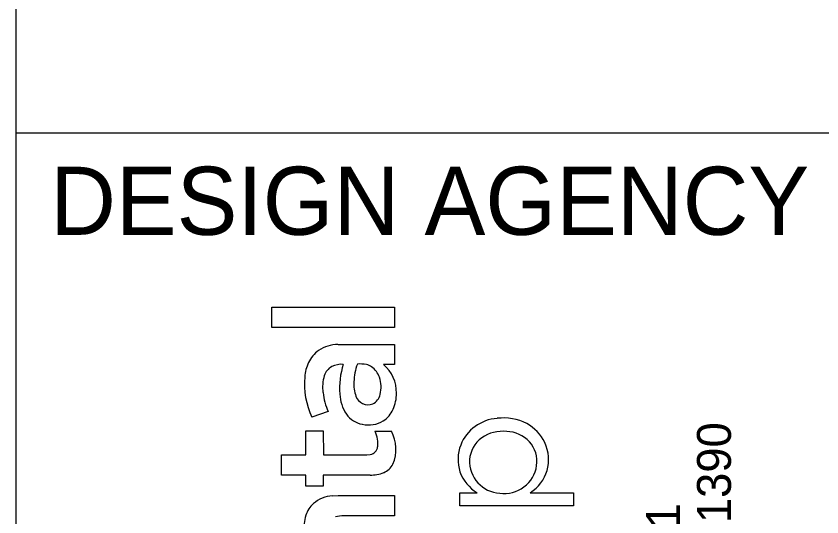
# Model space of a CAD drawing. Extents: x -0.6 to 34, y 0 to 22.
# Drawn here: x 32 to 33.183, y 3.936 to 4.671 of the extents above; entities that cross this region are included whole.
import ezdxf

# ---------------------------------------------------------------- set-up
doc = ezdxf.new("R2010")
doc.units = 0
doc.layers.add('SH_Cut_Line', color=7, linetype='Continuous')
doc.layers.add('SH_Data', color=7, linetype='Continuous')

msp = doc.modelspace()

# ---------------------------------------------------------------- linework, layer by layer
at = {"layer": 'SH_Cut_Line'}
for p, q in [((32.3756, 4.2141), (32.3756, 4.244)), ((32.3756, 4.244), (32.5557, 4.244)), ((32.5557, 4.244), (32.5557, 4.2141)), ((32.5557, 4.2141), (32.3756, 4.2141)), ((32.4727, 4.189), (32.5555, 4.1892)), ((32.5555, 4.1892), (32.5557, 4.1596)), ((32.5557, 4.1596), (32.5397, 4.1596)), ((32.4582, 4.0904), (32.4343, 4.0823)), ((32.4254, 4.027), (32.4255, 4.0621)), ((32.4255, 4.0621), (32.4511, 4.0621)), ((32.4511, 4.0621), (32.4512, 4.027)), ((32.527, 4.0616), (32.5511, 4.0616)), ((32.3896, 3.9972), (32.3896, 4.027)), ((32.3896, 4.027), (32.4254, 4.027)), ((32.4512, 4.027), (32.515, 4.027)), ((32.515, 4.027), (32.52, 4.0275)), ((32.4254, 3.9972), (32.3896, 3.9972)), ((32.4254, 3.9807), (32.4254, 3.9972)), ((32.5197, 3.9972), (32.4511, 3.9972)), ((32.4511, 3.9972), (32.4511, 3.9807)), ((32.4511, 3.9807), (32.4254, 3.9807)), ((32.4644, 3.9669), (32.4729, 3.9673)), ((32.4729, 3.9673), (32.5557, 3.9673)), ((32.5557, 3.9673), (32.5557, 3.9375)), ((32.6515, 3.9521), (32.6515, 3.9711)), ((32.6515, 3.9711), (32.6771, 3.9711)), ((32.7549, 3.9713), (32.8186, 3.9711)), ((32.8186, 3.9711), (32.8184, 3.9521)), ((32.8184, 3.9521), (32.6515, 3.9521)), ((32.5557, 3.9375), (32.4814, 3.9375))]:
    msp.add_line(p, q, dxfattribs=at)
msp.add_lwpolyline([(32.3756, 4.2141), (32.3756, 4.244), (32.5557, 4.244), (32.5557, 4.2141)], close=True, dxfattribs=at)
for points in [[(32.4727, 4.189), (32.5555, 4.1892), (32.5557, 4.1596)], [(32.5557, 4.1596), (32.5397, 4.1596)], [(32.4582, 4.0904), (32.4343, 4.0823)], [(32.5197, 3.9972), (32.4511, 3.9972), (32.4511, 3.9807), (32.4254, 3.9807), (32.4254, 3.9972), (32.3896, 3.9972), (32.3896, 4.027), (32.4254, 4.027), (32.4255, 4.0621), (32.4511, 4.0621), (32.4512, 4.027), (32.515, 4.027), (32.52, 4.0275)], [(32.527, 4.0616), (32.5511, 4.0616)], [(32.4644, 3.9669), (32.4729, 3.9673), (32.5557, 3.9673), (32.5557, 3.9375), (32.4814, 3.9375)], [(32.7549, 3.9713), (32.8186, 3.9711), (32.8184, 3.9521), (32.6515, 3.9521)], [(32.6515, 3.9521), (32.6515, 3.9711), (32.6771, 3.9711)]]:
    msp.add_lwpolyline(points, dxfattribs=at)
for centre, radius, start, end in [((32.4745, 4.1326), 0.0565, 91.8942, 122.6317), ((32.4745, 4.1326), 0.0565, 91.8942, 122.6317), ((32.4685, 4.1447), 0.043, 124.537, 155.6594), ((32.4685, 4.1447), 0.043, 124.537, 155.6594), ((32.4882, 4.1361), 0.0646, 155.9764, 175.3149), ((32.4882, 4.1361), 0.0646, 155.9764, 175.3149), ((32.4753, 4.1356), 0.024, 119.4252, 161.6629), ((32.4753, 4.1356), 0.024, 119.4252, 161.6629), ((32.4779, 4.1278), 0.0321, 85.3802, 116.6222), ((32.4779, 4.1278), 0.0321, 85.3802, 116.6222), ((32.5879, 4.1251), 0.1129, 162.0821, 184.5285), ((32.5879, 4.1251), 0.1129, 162.0821, 184.5285), ((32.5801, 4.1313), 0.0841, 159.8366, 178.0362), ((32.5801, 4.1313), 0.0841, 159.8366, 178.0362), ((32.5051, 4.1074), 0.053, 79.6696, 94.2322), ((32.5051, 4.1074), 0.053, 79.6696, 94.2322), ((32.5089, 4.1364), 0.0238, 56.8913, 76.2149), ((32.5089, 4.1364), 0.0238, 56.8913, 76.2149), ((32.5052, 4.1318), 0.0297, 17.5984, 55.7282), ((32.5052, 4.1318), 0.0297, 17.5984, 55.7282), ((32.5055, 4.1191), 0.0529, 358.0746, 49.762), ((32.5055, 4.1191), 0.0529, 358.0746, 49.762), ((32.5364, 4.1308), 0.113, 174.6101, 205.3899), ((32.5364, 4.1308), 0.113, 174.6101, 205.3899), ((32.5076, 4.1265), 0.0576, 163.1369, 188.1675), ((32.5076, 4.1265), 0.0576, 163.1369, 188.1675), ((32.5466, 4.1303), 0.0506, 175.5903, 199.8857), ((32.5466, 4.1303), 0.0506, 175.5903, 199.8857), ((32.4916, 4.1264), 0.0443, 345.9408, 18.9919), ((32.4916, 4.1264), 0.0443, 345.9408, 18.9919), ((32.5473, 4.1297), 0.0973, 186.7598, 203.7981), ((32.5473, 4.1297), 0.0973, 186.7598, 203.7981), ((32.5328, 4.1187), 0.0575, 182.5676, 213.7144), ((32.5328, 4.1187), 0.0575, 182.5676, 213.7144), ((32.5164, 4.1189), 0.0184, 198.2844, 293.3081), ((32.5164, 4.1189), 0.0184, 198.2844, 293.3081), ((32.5152, 4.1199), 0.0199, 295.2883, 347.4639), ((32.5152, 4.1199), 0.0199, 295.2883, 347.4639), ((32.5019, 4.1168), 0.0566, 336.016, 0.5951), ((32.5019, 4.1168), 0.0566, 336.016, 0.5951), ((32.5149, 4.1078), 0.0366, 215.0668, 259.8133), ((32.5149, 4.1078), 0.0366, 215.0668, 259.8133), ((32.5175, 4.1097), 0.0394, 303.4436, 336.18), ((32.5175, 4.1097), 0.0394, 303.4436, 336.18), ((32.5175, 4.1131), 0.0423, 257.5256, 300.882), ((32.5175, 4.1131), 0.0423, 257.5256, 300.882), ((32.7108, 4.0182), 0.0624, 93.9866, 158.3119), ((32.7108, 4.0182), 0.0624, 93.9866, 158.3119), ((32.7156, 4.0065), 0.0746, 62.6889, 97.0135), ((32.7156, 4.0065), 0.0746, 62.6889, 97.0135), ((32.7212, 4.0191), 0.0608, 25.0657, 61.9602), ((32.7212, 4.0191), 0.0608, 25.0657, 61.9602), ((32.4863, 4.042), 0.0452, 10.1545, 25.723), ((32.4863, 4.042), 0.0452, 10.1545, 25.723), ((32.503, 4.0351), 0.0549, 336.589, 28.8991), ((32.503, 4.0351), 0.0549, 336.589, 28.8991), ((32.7138, 4.0102), 0.0513, 87.8965, 131.1812), ((32.7138, 4.0102), 0.0513, 87.8965, 131.1812), ((32.7175, 4.0102), 0.0513, 49.9089, 92.0363), ((32.7175, 4.0102), 0.0513, 49.9089, 92.0363), ((32.4957, 4.0436), 0.0356, 351.914, 10.2059), ((32.4957, 4.0436), 0.0356, 351.914, 10.2059), ((32.7092, 4.0167), 0.0434, 132.3289, 182.0949), ((32.7092, 4.0167), 0.0434, 132.3289, 182.0949), ((32.7215, 4.0173), 0.0433, 358.0487, 47.9447), ((32.7215, 4.0173), 0.0433, 358.0487, 47.9447), ((32.5184, 4.04), 0.0126, 277.6142, 353.7918), ((32.5184, 4.04), 0.0126, 277.6142, 353.7918), ((32.707, 4.0202), 0.0581, 158.656, 198.171), ((32.707, 4.0202), 0.0581, 158.656, 198.171), ((32.7245, 4.02), 0.0574, 301.9776, 25.6418), ((32.7245, 4.02), 0.0574, 301.9776, 25.6418), ((32.5291, 4.0261), 0.0275, 292.6889, 332.0598), ((32.5291, 4.0261), 0.0275, 292.6889, 332.0598), ((32.7135, 4.0181), 0.0478, 183.5974, 271.7045), ((32.7135, 4.0181), 0.0478, 183.5974, 271.7045), ((32.7172, 4.018), 0.0477, 267.3149, 357.4019), ((32.7172, 4.018), 0.0477, 267.3149, 357.4019), ((32.5209, 4.0486), 0.0514, 268.6727, 291.5235), ((32.5209, 4.0486), 0.0514, 268.6727, 291.5235), ((32.7103, 4.0243), 0.0627, 200.8399, 238.0162), ((32.7103, 4.0243), 0.0627, 200.8399, 238.0162), ((32.4687, 3.9172), 0.0499, 94.9706, 130.2248), ((32.4687, 3.9172), 0.0499, 94.9706, 130.2248), ((32.4635, 3.9255), 0.0402, 132.2238, 161.6823), ((32.4635, 3.9255), 0.0402, 132.2238, 161.6823), ((32.4787, 3.9211), 0.056, 162.274, 187.7917), ((32.4787, 3.9211), 0.056, 162.274, 187.7917), ((32.4811, 3.8915), 0.046, 89.6051, 105.3303), ((32.4811, 3.8915), 0.046, 89.6051, 105.3303)]:
    msp.add_arc(centre, radius, start, end, dxfattribs=at)
at = {"layer": 'SH_Data'}
for p, q in [((32, 0.5), (32, 21.5)), ((32, 4.5), (33.5, 4.5))]:
    msp.add_line(p, q, dxfattribs=at)

# ---------------------------------------------------------------- texts
at = {"layer": 'SH_Cut_Line'}
msp.add_text('DESIGN AGENCY', height=0.1, dxfattribs=at).set_placement((32.05, 4.35))
for s, p in [('800.835.1390', (33.0497, 3.6671)), ('450 GRANT ST., AKRON, OH  44311', (32.9749, 2.8374))]:
    msp.add_text(s, height=0.049846, rotation=90, dxfattribs=at).set_placement(p)

doc.saveas('drawing.dxf')
